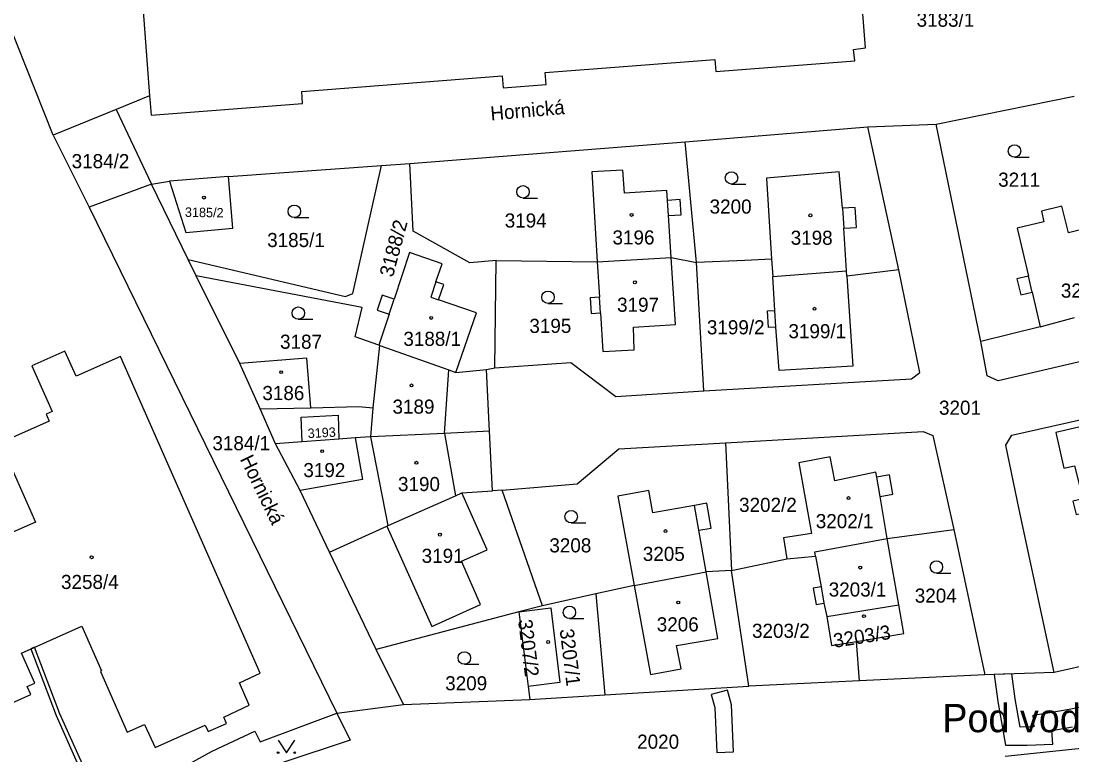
# Model space of a CAD drawing. Extents: x -869103 to -863415, y -1015889 to -1012477.
# Drawn here: x -866433.6 to -866307, y -1014429.4 to -1014341 of the extents above; entities that cross this region are included whole.
import ezdxf

# ---------------------------------------------------------------- set-up
doc = ezdxf.new("R2010")
doc.units = 0
for name, color, linetype in [('Hranice parcel', 7, 'Continuous'), ('Parcelní čísla', 7, 'Continuous'), ('Pop  PČ popisy', 7, 'Continuous'), ('Vnitřní kresba', 7, 'Continuous'), ('Věcná břemena k části', 7, 'Continuous'), ('Značky budov', 7, 'Continuous'), ('Značky kultur', 7, 'Continuous')]:
    doc.layers.add(name, color=color, linetype=linetype)

msp = doc.modelspace()

# ---------------------------------------------------------------- linework, layer by layer
at = {"layer": 'Hranice parcel'}
for p, q in [((-866419.47, -1014332.26), (-866418.1, -1014350)), ((-866418.1, -1014350), (-866422.15, -1014351.65)), ((-866418.1, -1014350), (-866418.03, -1014350.88)), ((-866323.35, -1014353.41), (-866306.72, -1014350.04)), ((-866422.15, -1014351.65), (-866429.74, -1014354.75)), ((-866422.15, -1014351.65), (-866417.88, -1014360.64)), ((-866353.56, -1014355.54), (-866331.58, -1014353.75)), ((-866331.58, -1014353.75), (-866323.35, -1014353.41)), ((-866327.84, -1014370.98), (-866331.58, -1014353.75)), ((-866317.94, -1014379.63), (-866323.35, -1014353.41)), ((-866429.74, -1014354.75), (-866425.39, -1014363.43)), ((-866386.76, -1014358.18), (-866353.56, -1014355.54)), ((-866352.23, -1014370.1), (-866353.56, -1014355.54)), ((-866408.6, -1014359.71), (-866390.15, -1014358.42)), ((-866393.61, -1014373.84), (-866390.15, -1014358.42)), ((-866390.15, -1014358.42), (-866386.76, -1014358.18)), ((-866417.88, -1014360.64), (-866415.7, -1014360.29)), ((-866408.6, -1014359.71), (-866415.7, -1014360.29)), ((-866417.88, -1014360.64), (-866425.39, -1014363.43)), ((-866413.46, -1014369.74), (-866417.88, -1014360.64)), ((-866425.39, -1014363.43), (-866395.53, -1014424.41)), ((-866412.5, -1014371.7), (-866413.46, -1014369.74)), ((-866413.46, -1014369.74), (-866394.51, -1014374.2)), ((-866376.5, -1014382.77), (-866376.36, -1014369.87)), ((-866376.36, -1014369.87), (-866364.16, -1014370)), ((-866364.16, -1014370), (-866355.26, -1014369.49)), ((-866355.26, -1014369.49), (-866352.23, -1014370.1)), ((-866346.4, -1014369.87), (-866352.23, -1014370.1)), ((-866351.34, -1014385.57), (-866352.23, -1014370.1)), ((-866343.16, -1014369.68), (-866346.4, -1014369.87)), ((-866343.16, -1014369.68), (-866343.03, -1014371.77)), ((-866407.25, -1014382.25), (-866412.5, -1014371.7)), ((-866343.03, -1014371.77), (-866334.13, -1014371.1)), ((-866334.09, -1014371.75), (-866334.13, -1014371.1)), ((-866327.84, -1014370.98), (-866334.09, -1014371.75)), ((-866394.51, -1014374.2), (-866393.61, -1014373.84)), ((-866390.37, -1014380.1), (-866390.48, -1014380.06)), ((-866404.8, -1014387.73), (-866407.25, -1014382.25)), ((-866381.19, -1014383.34), (-866377.52, -1014382.98)), ((-866377.52, -1014382.98), (-866376.5, -1014382.77)), ((-866377.16, -1014390.41), (-866377.52, -1014382.98)), ((-866351.34, -1014385.57), (-866326.31, -1014384.11)), ((-866404.8, -1014387.73), (-866398.69, -1014387.59)), ((-866402.93, -1014391.94), (-866404.8, -1014387.73)), ((-866376.81, -1014397.62), (-866377.16, -1014390.41)), ((-866348.73, -1014391.82), (-866324.91, -1014390.46)), ((-866399.73, -1014391.7), (-866402.93, -1014391.94)), ((-866399.95, -1014397.57), (-866402.93, -1014391.94)), ((-866395.29, -1014391.37), (-866399.73, -1014391.7)), ((-866393.35, -1014391.23), (-866395.29, -1014391.37)), ((-866348.73, -1014391.82), (-866348, -1014407.2)), ((-866396.45, -1014404.99), (-866399.95, -1014397.57)), ((-866375.61, -1014397.52), (-866376.81, -1014397.62)), ((-866370.75, -1014411.47), (-866375.61, -1014397.52)), ((-866329.22, -1014403.34), (-866321.19, -1014402.27)), ((-866327.83, -1014411.33), (-866329.22, -1014403.34)), ((-866321.19, -1014402.27), (-866317.45, -1014419.78)), ((-866390.81, -1014416.74), (-866396.45, -1014404.99)), ((-866348, -1014407.2), (-866341.31, -1014405.79)), ((-866341.31, -1014405.79), (-866337.86, -1014405.5)), ((-866359.73, -1014409), (-866351.06, -1014407.39)), ((-866348, -1014407.2), (-866351.06, -1014407.39)), ((-866345.9, -1014421.16), (-866348, -1014407.2)), ((-866359.73, -1014409), (-866364.35, -1014410.04)), ((-866364.35, -1014410.04), (-866370.75, -1014411.47)), ((-866364.35, -1014410.04), (-866363.26, -1014422.2)), ((-866373.61, -1014412.19), (-866390.81, -1014416.74)), ((-866370.75, -1014411.47), (-866373.61, -1014412.19)), ((-866373.61, -1014412.19), (-866372.5, -1014421.19)), ((-866336.52, -1014412.77), (-866327.83, -1014411.33)), ((-866332.58, -1014420.51), (-866332.92, -1014415.75)), ((-866291.04, -1014415.48), (-866309.13, -1014419.49)), ((-866387.53, -1014423.37), (-866390.81, -1014416.74)), ((-866317.45, -1014419.78), (-866332.58, -1014420.51)), ((-866309.13, -1014419.49), (-866317.45, -1014419.78)), ((-866332.58, -1014420.51), (-866345.9, -1014421.16)), ((-866372.5, -1014421.19), (-866372.31, -1014422.74)), ((-866372.31, -1014422.74), (-866363.26, -1014422.2)), ((-866363.26, -1014422.2), (-866345.9, -1014421.16)), ((-866395.53, -1014424.41), (-866387.53, -1014423.37)), ((-866387.53, -1014423.37), (-866372.31, -1014422.74)), ((-866304.7, -1014428.53), (-866315.02, -1014429.62))]:
    msp.add_line(p, q, dxfattribs=at)
for points in [[(-866429.74, -1014354.75), (-866439.51, -1014330.13), (-866441.35, -1014322.65), (-866446.48, -1014291.07)], [(-866418.03, -1014350.88), (-866417.91, -1014352.33), (-866399.67, -1014350.92), (-866399.78, -1014349.47), (-866375.61, -1014347.6), (-866375.5, -1014349.04), (-866370.34, -1014348.65), (-866370.46, -1014347.2), (-866349.99, -1014345.62), (-866349.88, -1014347.06), (-866333.13, -1014345.77), (-866333.29, -1014344.44), (-866331.85, -1014344.21), (-866332.81, -1014331.85), (-866334.21, -1014331.95), (-866334.69, -1014325.86)], [(-866376.36, -1014369.87), (-866379.54, -1014370.14), (-866386.33, -1014366.3), (-866386.76, -1014358.18)], [(-866355.26, -1014369.49), (-866355.59, -1014364.44), (-866354.07, -1014364.34), (-866354.19, -1014362.51), (-866355.7, -1014362.61), (-866355.78, -1014361.42), (-866360.9, -1014361.75), (-866361.09, -1014358.95), (-866364.81, -1014359.16), (-866364.16, -1014370)], [(-866415.7, -1014360.29), (-866413.76, -1014366.48), (-866408.07, -1014365.95), (-866408.6, -1014359.71)], [(-866334.13, -1014371.1), (-866334.46, -1014365.97), (-866332.93, -1014365.88), (-866333.08, -1014363.46), (-866334.61, -1014363.56), (-866335.03, -1014359.18), (-866343.77, -1014359.91), (-866343.16, -1014369.68)], [(-866307.38, -1014366.52), (-866308.18, -1014363.31), (-866310.66, -1014363.89), (-866310.35, -1014365.2), (-866313.57, -1014365.95)], [(-866296.94, -1014374.44), (-866297.32, -1014374.5), (-866299.23, -1014366.81), (-866299.81, -1014366.95), (-866300.25, -1014365.18), (-866300.52, -1014365.25), (-866300.74, -1014364.38), (-866301.77, -1014364.59), (-866301.56, -1014365.47), (-866301.97, -1014365.57), (-866301.81, -1014366.21), (-866303.22, -1014366.56), (-866302.93, -1014367.73), (-866303.32, -1014367.82), (-866303.86, -1014365.65), (-866307.38, -1014366.52)], [(-866313.57, -1014365.95), (-866312.21, -1014371.74), (-866313.6, -1014372.07), (-866313.15, -1014374), (-866311.76, -1014373.68), (-866310.79, -1014377.83), (-866317.94, -1014379.63)], [(-866381.19, -1014383.34), (-866378.73, -1014376.15), (-866383.28, -1014374.59), (-866382.64, -1014372.74), (-866383.6, -1014372.42), (-866382.87, -1014370.26), (-866386.78, -1014368.88), (-866388.65, -1014374.52), (-866390.1, -1014374.04), (-866390.7, -1014375.85), (-866389.24, -1014376.33), (-866390.48, -1014380.06)], [(-866364.16, -1014370), (-866363.9, -1014374.29), (-866365.02, -1014374.36), (-866364.91, -1014376.23), (-866363.78, -1014376.16), (-866363.5, -1014380.83), (-866359.71, -1014380.63), (-866359.79, -1014377.88), (-866354.74, -1014377.55), (-866355.26, -1014369.49)], [(-866390.48, -1014380.06), (-866393.32, -1014379.04), (-866392.48, -1014375.53), (-866412.5, -1014371.7)], [(-866326.31, -1014384.11), (-866325.31, -1014383.33), (-866327.84, -1014370.98)], [(-866334.09, -1014371.75), (-866333.37, -1014382.57), (-866342.23, -1014383.09), (-866342.65, -1014377.87), (-866343.54, -1014377.93), (-866343.67, -1014375.92), (-866342.77, -1014375.86), (-866343.03, -1014371.77)], [(-866398.69, -1014387.59), (-866392.92, -1014387.45), (-866391.15, -1014387.61), (-866390.37, -1014380.1)], [(-866390.37, -1014380.1), (-866382.04, -1014383.04), (-866381.19, -1014383.34)], [(-866300.21, -1014380.71), (-866315.86, -1014384.35), (-866317.2, -1014383.74), (-866317.94, -1014379.63)], [(-866431.95, -1014420.77), (-866433.55, -1014417.16), (-866426.26, -1014413.94), (-866423.89, -1014419.32), (-866424.03, -1014419.38), (-866420.8, -1014426.69), (-866418.71, -1014425.76), (-866417.45, -1014428.56), (-866411.4, -1014425.87), (-866411.07, -1014426.61), (-866408.85, -1014425.64), (-866409.18, -1014424.89), (-866406.1, -1014423.46), (-866407.27, -1014420.76), (-866404.77, -1014419.6), (-866421.61, -1014381.43), (-866426.97, -1014383.8), (-866428.31, -1014380.78), (-866432.28, -1014382.54), (-866429.84, -1014388.06), (-866430.58, -1014388.39), (-866430.21, -1014389.22), (-866436.07, -1014391.81), (-866431.85, -1014401.37), (-866435.61, -1014403.02)], [(-866398.69, -1014387.59), (-866399.15, -1014381.64), (-866407.25, -1014382.25)], [(-866376.5, -1014382.77), (-866367.35, -1014382.13), (-866361.95, -1014386.24), (-866351.34, -1014385.57)], [(-866309.13, -1014419.49), (-866313.34, -1014399.87), (-866314.94, -1014392.12), (-866314.23, -1014390.9), (-866294.2, -1014386.41), (-866293.31, -1014390.03)], [(-866305.67, -1014398.56), (-866306.88, -1014398.86), (-866306.48, -1014400.47), (-866305.27, -1014400.17), (-866303.9, -1014405.94), (-866299.82, -1014404.95), (-866300.22, -1014403.3), (-866298.46, -1014402.87), (-866299.06, -1014400.42), (-866295.25, -1014399.5), (-866297.06, -1014392.01), (-866293.19, -1014391.11), (-866294.32, -1014386.78), (-866298.1, -1014387.75), (-866298.01, -1014388.05), (-866308.91, -1014390.6), (-866307.95, -1014394.88), (-866306.68, -1014394.59), (-866305.67, -1014398.56)], [(-866399.73, -1014391.7), (-866399.83, -1014388.75), (-866395.39, -1014388.48), (-866395.29, -1014391.37)], [(-866377.16, -1014390.41), (-866382.56, -1014390.69), (-866391.46, -1014391.09), (-866393.35, -1014391.23)], [(-866324.91, -1014390.46), (-866323.73, -1014390.95), (-866321.19, -1014402.27)], [(-866393.35, -1014391.23), (-866392.45, -1014396.23), (-866399.95, -1014397.57)], [(-866375.61, -1014397.52), (-866366.6, -1014396.78), (-866361.55, -1014392.55), (-866348.73, -1014391.82)], [(-866329.22, -1014403.34), (-866330.09, -1014398.28), (-866328.57, -1014398.01), (-866328.97, -1014395.7), (-866330.49, -1014395.96), (-866330.6, -1014395.35), (-866335.54, -1014396.42), (-866336.09, -1014393.5), (-866339.88, -1014394.23), (-866338.36, -1014402.76), (-866341.73, -1014403.29), (-866341.31, -1014405.79)], [(-866396.45, -1014404.99), (-866389.53, -1014401.88), (-866389.35, -1014401.8), (-866381.25, -1014398.2), (-866380.49, -1014397.86), (-866376.81, -1014397.62)], [(-866351.06, -1014407.39), (-866351.94, -1014402.36), (-866350.43, -1014402.09), (-866350.96, -1014399.11), (-866352.47, -1014399.38), (-866357.46, -1014400.26), (-866357.95, -1014397.57), (-866361.7, -1014398.25), (-866359.73, -1014409)], [(-866337.86, -1014405.5), (-866337.96, -1014404.97), (-866329.22, -1014403.34)], [(-866337.86, -1014405.5), (-866337.2, -1014409.17), (-866338.14, -1014409.34), (-866337.79, -1014411.31), (-866336.85, -1014411.14), (-866336.52, -1014412.77)], [(-866373.61, -1014412.19), (-866369.77, -1014411.72), (-866368.66, -1014420.72), (-866372.5, -1014421.19)], [(-866332.92, -1014415.75), (-866327.22, -1014414.79), (-866327.83, -1014411.33)], [(-866336.52, -1014412.77), (-866335.93, -1014416.26), (-866332.92, -1014415.75)], [(-866442.48, -1014426.65), (-866432.43, -1014422.17), (-866432.87, -1014421.18), (-866431.95, -1014420.77)], [(-866465.23, -1014439.67), (-866451.48, -1014441.96), (-866436.37, -1014440.19), (-866420.04, -1014434.21), (-866410.57, -1014428.99), (-866405.42, -1014426.56), (-866404.79, -1014427.86), (-866395.53, -1014424.41)], [(-866395.53, -1014424.41), (-866393.94, -1014427.66), (-866442.66, -1014443.81), (-866454.8, -1014442.43)]]:
    msp.add_lwpolyline(points, dxfattribs=at)
at = {"layer": 'Vnitřní kresba'}
for p, q in [((-866355.59, -1014364.44), (-866355.7, -1014362.61)), ((-866334.61, -1014363.56), (-866334.46, -1014365.97)), ((-866383.6, -1014372.42), (-866384.23, -1014374.27)), ((-866311.76, -1014373.68), (-866312.21, -1014371.74)), ((-866389.24, -1014376.33), (-866388.65, -1014374.52)), ((-866384.23, -1014374.27), (-866383.28, -1014374.59)), ((-866363.78, -1014376.16), (-866363.9, -1014374.29)), ((-866342.65, -1014377.87), (-866342.77, -1014375.86)), ((-866310.79, -1014377.83), (-866306.65, -1014376.73)), ((-866382.56, -1014390.69), (-866382.04, -1014383.04)), ((-866391.46, -1014391.09), (-866391.15, -1014387.61)), ((-866382.56, -1014390.69), (-866381.25, -1014398.2)), ((-866389.35, -1014401.8), (-866391.46, -1014391.09)), ((-866330.09, -1014398.28), (-866330.49, -1014395.96)), ((-866377.44, -1014404.74), (-866380.49, -1014397.86)), ((-866351.94, -1014402.36), (-866352.47, -1014399.38)), ((-866389.53, -1014401.88), (-866384.12, -1014413.96)), ((-866380.51, -1014406.08), (-866377.44, -1014404.74)), ((-866378.24, -1014411.31), (-866380.51, -1014406.08)), ((-866349.64, -1014415.39), (-866351.06, -1014407.39)), ((-866359.73, -1014409), (-866357.75, -1014419.75)), ((-866337.2, -1014409.17), (-866336.85, -1014411.14)), ((-866384.12, -1014413.96), (-866378.24, -1014411.31)), ((-866354.61, -1014416.27), (-866349.64, -1014415.39)), ((-866354.05, -1014419.07), (-866354.61, -1014416.27)), ((-866357.75, -1014419.75), (-866354.05, -1014419.07))]:
    msp.add_line(p, q, dxfattribs=at)
at = {"layer": 'Věcná břemena k části'}
for points in [[(-866432.42, -1014416.66), (-866429.37, -1014424.67), (-866426.82, -1014430.4), (-866424.67, -1014435.91), (-866424, -1014437.63), (-866423.53, -1014437.47), (-866424.21, -1014435.74), (-866426.36, -1014430.2), (-866428.91, -1014424.48), (-866431.96, -1014416.46)], [(-866350.44, -1014422.17), (-866350.02, -1014423.73), (-866349.78, -1014429.16), (-866347.74, -1014429.06), (-866348, -1014423.42), (-866348.46, -1014421.65)]]:
    msp.add_lwpolyline(points, close=True, dxfattribs=at)
msp.add_lwpolyline([(-866297.13, -1014421.89), (-866307.29, -1014423.95), (-866310.12, -1014424.43), (-866311.7, -1014424.67), (-866311.58, -1014426.07), (-866313.22, -1014426.1), (-866313.82, -1014422.67), (-866314.21, -1014419.67), (-866316.34, -1014419.74), (-866315.92, -1014422.99), (-866314.99, -1014428.28), (-866314.1, -1014428.25), (-866312.35, -1014428.27), (-866309.26, -1014428.13), (-866309.38, -1014426.5), (-866306.89, -1014426.07)], dxfattribs=at)
at = {"layer": 'Značky budov'}
for centre in [(-866411.56, -1014362.27), (-866360.03, -1014364.36), (-866338.49, -1014364.41), (-866359.63, -1014372.48), (-866337.99, -1014375.66), (-866384.18, -1014376.77), (-866402.26, -1014383.31), (-866386.55, -1014384.9), (-866397.32, -1014392.83), (-866385.96, -1014394.23), (-866333.89, -1014398.48), (-866383.12, -1014402.89), (-866355.95, -1014402.46), (-866425.09, -1014405.62), (-866332.48, -1014406.86), (-866354.41, -1014411.07), (-866332.03, -1014412.72), (-866370.08, -1014415.83)]:
    msp.add_circle(centre, 0.175, dxfattribs=at)
at = {"layer": 'Značky kultur'}
for p, q in [((-866313.89, -1014357.41), (-866312.14, -1014357.41)), ((-866348, -1014360.65), (-866346.25, -1014360.65)), ((-866373.11, -1014362.33), (-866371.36, -1014362.33)), ((-866400.67, -1014364.68), (-866398.92, -1014364.68)), ((-866370.1, -1014375.03), (-866368.35, -1014375.03)), ((-866400.19, -1014376.94), (-866398.44, -1014376.94)), ((-866367.31, -1014401.48), (-866365.56, -1014401.48)), ((-866323.3, -1014407.54), (-866321.55, -1014407.54)), ((-866367.52, -1014413.01), (-866365.77, -1014413.01)), ((-866380.18, -1014418.5), (-866378.43, -1014418.5))]:
    msp.add_line(p, q, dxfattribs=at)
msp.add_lwpolyline([(-866402.62, -1014427.67), (-866401.62, -1014429.17), (-866400.62, -1014427.67)], dxfattribs=at)
for centre, radius in [((-866313.89, -1014356.66), 0.75), ((-866348, -1014359.9), 0.75), ((-866373.11, -1014361.58), 0.75), ((-866400.67, -1014363.93), 0.75), ((-866370.1, -1014374.28), 0.75), ((-866400.19, -1014376.19), 0.75), ((-866367.31, -1014400.73), 0.75), ((-866323.3, -1014406.79), 0.75), ((-866367.52, -1014412.26), 0.75), ((-866380.18, -1014417.75), 0.75), ((-866402.62, -1014429.17), 0.1), ((-866400.62, -1014429.17), 0.1)]:
    msp.add_circle(centre, radius, dxfattribs=at)

# ---------------------------------------------------------------- texts
at = {"layer": 'Parcelní čísla'}
for s, p in [('3183/1', (-866325.69, -1014341.68)), ('3184/2', (-866427.5, -1014358.73)), ('3211', (-866315.86, -1014360.96)), ('3200', (-866350.63, -1014364.2)), ('3194', (-866375.32, -1014365.88)), ('3185/1', (-866403.94, -1014368.23)), ('3196', (-866362.33, -1014367.92)), ('3198', (-866340.86, -1014367.96)), ('3210', (-866308.31, -1014374.33)), ('3197', (-866361.78, -1014376.03)), ('3195', (-866372.35, -1014378.58)), ('3199/2', (-866350.96, -1014378.75)), ('3199/1', (-866341.13, -1014379.22)), ('3187', (-866402.39, -1014380.49)), ('3188/1', (-866387.53, -1014380.14)), ('3186', (-866404.52, -1014386.67)), ('3189', (-866388.84, -1014388.31)), ('3201', (-866322.99, -1014388.44)), ('3184/1', (-866410.54, -1014392.72)), ('3192', (-866399.58, -1014395.96)), ('3190', (-866388.18, -1014397.64)), ('3202/2', (-866347.08, -1014400.15)), ('3202/1', (-866337.84, -1014402.11)), ('3208', (-866369.94, -1014405.03)), ('3191', (-866385.33, -1014406.29)), ('3205', (-866358.68, -1014406.06)), ('3258/4', (-866428.78, -1014409.44)), ('3203/1', (-866336.28, -1014410.35)), ('3204', (-866325.91, -1014411.09)), ('3206', (-866357, -1014414.55)), ('3203/2', (-866345.52, -1014415.33)), ('3209', (-866382.49, -1014421.65)), ('2020', (-866359.36, -1014428.69))]:
    msp.add_text(s, height=1.7, dxfattribs=at).set_placement(p)
for s, height, rotation, p in [('3185/2', 1.139, 359, (-866413.86, -1014364.59)), ('3188/2', 1.7, 75, (-866388.8, -1014371.95)), ('3193', 1.139, 3, (-866399.03, -1014391.26)), ('3207/2', 1.7, 277, (-866373.71, -1014413.2)), ('3207/1', 1.7, 277, (-866368.7, -1014414.33)), ('3203/3', 1.7, 9, (-866335.58, -1014416.53))]:
    msp.add_text(s, height=height, rotation=rotation, dxfattribs=at).set_placement(p)
at = {"layer": 'Pop  PČ popisy'}
for rotation, p in [(5, (-866376.97, -1014352.98)), (296, (-866407.26, -1014393.79))]:
    msp.add_text('Hornická', height=1.7, rotation=rotation, dxfattribs=at).set_placement(p)
msp.add_text('Pod vodojemem', height=3.4, dxfattribs=at).set_placement((-866322.59, -1014426.7))

doc.saveas('drawing.dxf')
